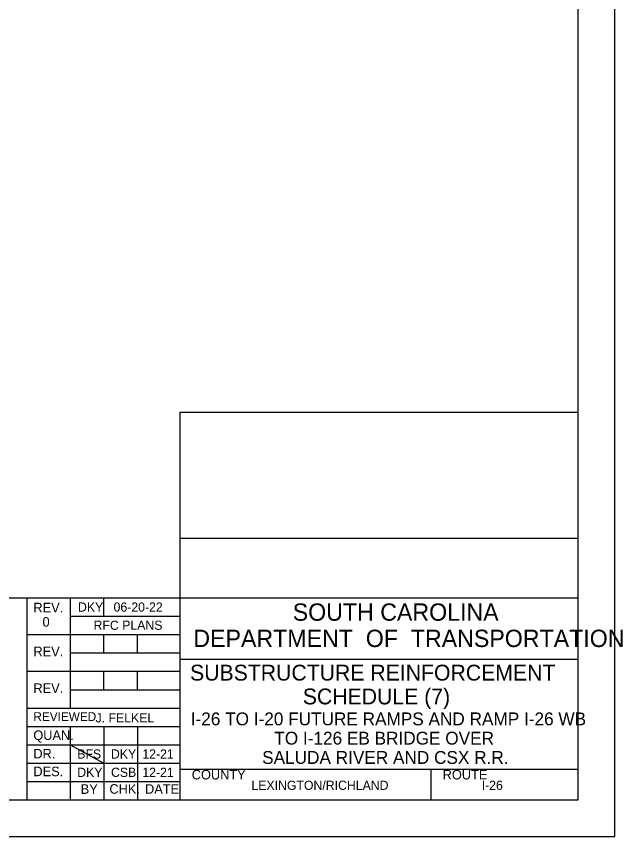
# Model space of a CAD drawing. Extents: x -121.2 to -24.9, y 6.4 to 65.9.
# Drawn here: x -46.89 to -24.88, y 6.35 to 36.13 of the extents above; entities that cross this region are included whole.
import ezdxf

# ---------------------------------------------------------------- set-up
doc = ezdxf.new("R2010")
doc.units = 0
for name, color, linetype in [('BR_BORDER LINES', 7, 'Continuous'), ('BR_TEXT', 7, 'Continuous'), ('Level 31', 7, 'Continuous')]:
    doc.layers.add(name, color=color, linetype=linetype)

msp = doc.modelspace()

# ---------------------------------------------------------------- linework, layer by layer
at = {"layer": 'BR_BORDER LINES'}
for p, q in [((-26.496, 7.683), (-26.496, 63.683)), ((-40.941, 7.683), (-40.941, 21.754)), ((-40.941, 21.754), (-26.496, 21.754)), ((-40.94, 17.182), (-26.496, 17.182)), ((-60.804, 15.017), (-46.496, 15.017)), ((-46.496, 7.683), (-46.496, 15.017)), ((-46.496, 15.017), (-26.496, 15.017)), ((-44.941, 15.017), (-44.941, 11.017)), ((-43.718, 14.35), (-43.718, 15.017)), ((-44.941, 14.35), (-40.941, 14.35)), ((-46.496, 13.684), (-40.941, 13.684)), ((-43.718, 13.017), (-43.718, 13.684)), ((-42.496, 13.017), (-42.496, 13.684)), ((-44.941, 13.017), (-40.941, 13.017)), ((-40.941, 12.795), (-40.941, 12.795)), ((-40.941, 12.795), (-26.495, 12.795)), ((-46.496, 12.35), (-40.941, 12.35)), ((-43.718, 11.684), (-43.718, 12.35)), ((-42.496, 11.684), (-42.496, 12.35)), ((-44.941, 11.684), (-40.941, 11.684)), ((-46.496, 11.017), (-40.941, 11.017)), ((-46.496, 10.35), (-40.941, 10.35)), ((-44.941, 10.35), (-44.941, 7.683)), ((-43.718, 10.35), (-43.718, 7.683)), ((-42.496, 10.35), (-42.496, 7.683)), ((-46.496, 9.683), (-40.941, 9.683)), ((-46.496, 9.017), (-40.941, 9.017)), ((-40.941, 8.795), (-26.496, 8.795)), ((-40.68, 8.795), (-26.496, 8.795)), ((-31.829, 7.683), (-31.829, 8.795)), ((-46.496, 8.35), (-40.941, 8.35)), ((-116.272, 7.683), (-26.496, 7.683))]:
    msp.add_line(p, q, dxfattribs=at)
at = {"layer": 'Level 31'}
for p, q in [((-33.717, 11.621), (-33.717, 11.621)), ((-44.941, 9.683), (-43.718, 9.017))]:
    msp.add_line(p, q, dxfattribs=at)
msp.add_lwpolyline([(-121.161, 6.35), (-25.161, 6.35), (-25.161, 65.017), (-121.161, 65.017)], close=True, dxfattribs=at)

# ---------------------------------------------------------------- texts
at = {"layer": 'BR_TEXT'}
for s, height, p in [('REV.', 0.3467, (-46.27, 14.491)), ('DKY', 0.3333, (-44.652, 14.517)), ('06-20-22', 0.3333, (-43.36, 14.517)), ('SOUTH CAROLINA', 0.62899, (-36.855, 14.186)), ('0', 0.347, (-45.94, 13.971)), ('RFC PLANS', 0.3333, (-44.087, 13.857)), ('DEPARTMENT  OF  TRANSPORTATION', 0.62899, (-40.463, 13.232)), ('REV.', 0.3467, (-46.27, 12.898)), ('SUBSTRUCTURE REINFORCEMENT', 0.576, (-40.583, 12.014)), ('REV.', 0.3467, (-46.27, 11.565)), ('SCHEDULE (7)', 0.576, (-36.489, 11.15)), ('REVIEWED', 0.32, (-46.272, 10.546)), ('J. FELKEL', 0.3333, (-44.015, 10.495)), ('I-26 TO I-20 FUTURE RAMPS AND RAMP I-26 WB', 0.46667, (-40.558, 10.39)), ('QUAN.', 0.3467, (-46.274, 9.857)), ('TO I-126 EB BRIDGE OVER', 0.46667, (-37.523, 9.69)), ('DR.', 0.3467, (-46.273, 9.186)), ('BFS', 0.3333, (-44.677, 9.183)), ('DKY', 0.3333, (-43.456, 9.183)), ('12-21', 0.3333, (-42.316, 9.183)), ('SALUDA RIVER AND CSX R.R.', 0.46667, (-37.965, 8.99)), ('DES.', 0.3467, (-46.271, 8.543)), ('DKY', 0.3333, (-44.679, 8.517)), ('CSB', 0.3333, (-43.454, 8.517)), ('12-21', 0.3333, (-42.316, 8.517)), ('COUNTY', 0.3467, (-40.521, 8.425)), ('ROUTE', 0.3467, (-31.41, 8.425)), ('LEXINGTON/RICHLAND', 0.33332, (-38.355, 8.047)), ('I-26', 0.3333, (-29.993, 8.047)), ('BY', 0.3467, (-44.553, 7.902)), ('CHK.', 0.3467, (-43.511, 7.906)), ('DATE', 0.3467, (-42.217, 7.906))]:
    msp.add_text(s, height=height, dxfattribs=at).set_placement(p)

doc.saveas('drawing.dxf')
